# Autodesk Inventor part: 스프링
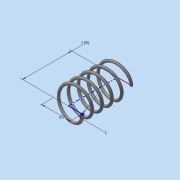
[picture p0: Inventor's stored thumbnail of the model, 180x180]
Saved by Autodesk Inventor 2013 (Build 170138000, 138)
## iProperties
Created: 2015-10
Part Number: 스프링
Material: 일반
Document SubType Name: Modeling
Designer: dgall
Density: 1 g/cm^3
Author: dgall
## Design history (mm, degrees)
sketch "스케치1"
  geometry: L1 (0, 0)-(0, 19); L2 (0, 19)-(5.5, 19); L3 (0, 0)-(5.5, 0); C1 r 0.5 at (5.5, 0)
  constraints: 6 end point, 1 centre point, 1 coincident, 1 parallel, 1 perpendicular, 1 vertical, 1 vertical alignment
  dimensions: "d0" = 1 diameter of C1; "d1" = 19 distance of L1.start L1.end (derived); "d2" = 11 diameter of L3.end L1
feature "코일1" pitch "d3" = 10; turns "d5" = 5; dims "d4" = 19 (= d1), "d6" = 0, angle "d7" = 90 deg, angle "d8" = 90 deg, "d9" = 0, "d10" = 0
feature "분할1"
node "작업 평면1"
feature "분할2"
node "솔리드1"
other parameters: "d11" = 19
